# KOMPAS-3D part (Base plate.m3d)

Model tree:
1. X Axis
2. Y Axis
3. Z Axis
4. Origin
     Wall Thickness 1 = 1; Wall Thickness 2 = 1; Distance 2 = 10

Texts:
  Steel DIN 17102
  Three Point Plane
  Plane at Angle
  Line and Point Plane
  Axis through Two Vertices
  Axis of Feature
  Axis of Conical Surface
  Axis through Edge
  Trim by Surface
  Trim by Sketch
  Feature with No History
  Intersection Axis of Two Planes
  Two Line Plane
  Line and Face Plane
  Bend by line
  Hole in sheet body
  Cut in sheet body
  Point in CM
  Linear Dimension from Line to Point
  Surface Finish Symbol
  Geometric Tolerance Symbol
  Leader #1
  Leader #2
  Leader #3
  Shape Deviations and Datum
  Node point number
  Mark of coordination axis
  Node point designation
  Mark/Reference designation with leader
  Mark/reference designation on line
  Mark/Reference designation without leader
